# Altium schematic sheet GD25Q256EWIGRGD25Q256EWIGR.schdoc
size 127 x 101 mm
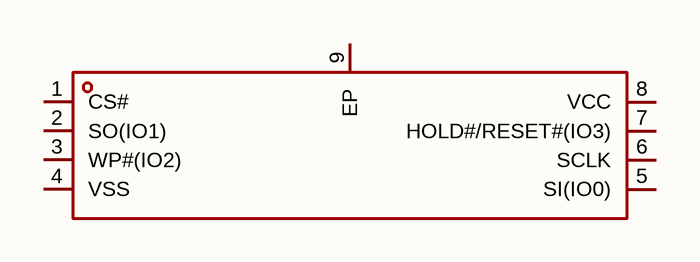
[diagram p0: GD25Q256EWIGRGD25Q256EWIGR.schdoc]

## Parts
U?  gd25q256ewigr  [WSON-8_L6.0-W5.0-P1.27-TL-EP]  (value not drawn)

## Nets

Not connected (* = marked no-connect by the designer): U? 1(CS#) 2(SO(IO1)) 3(WP#(IO2)) 4(VSS) 5(SI(IO0)) 6(SCLK) 7(HOLD#/RESET#(IO3)) 8(VCC) 9(EP)

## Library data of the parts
U? = gd25q256ewigr: 接口类型:SPI;存储容量:256Mbit;; Manufacturer: GigaDevice(兆易创新); AddInBom: yes; ModelId: 70c2d179fd41443b8a308a6a29aa356e; ModelTransform: 237.007,196.85,0,0,0,0,0,0,0; Interface: SPI; Voltage - Supply: 2.7V~3.6V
